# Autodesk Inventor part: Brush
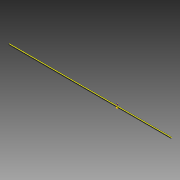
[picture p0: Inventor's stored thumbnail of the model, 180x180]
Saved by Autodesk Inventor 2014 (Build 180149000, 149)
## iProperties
Created: 2006-03
Part Number: Brush
Document SubType Name: Modeling
Designer: debonom
Material: Silicone
Mass: 8.74327 g
Surface Area: 94.4143 cm^2
Volume: 6.99461 cm^3
Density: 1.25 g/cm^3
Appearance: Rubber - Black - Version 1.1
Author: debonom
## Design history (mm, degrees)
sketch "Sketch1"
  geometry: L1 (0, 0)-(-2.332, 5); L2 (-2.332, 5)-(2.332, 5); L3 (2.332, 5)-(0, 0)
  constraints: 6 end point, 1 equal length, 1 horizontal
  dimensions: "d0" = 5 distance from line of L2 L1.start; "d2" = 50 deg angle of L3 L1
extrude "Extrusion1" new body sketch "Sketch1" distance "d3" = 200; taper "d4" = 0 deg
extrude "Extrusion2" join sketch "Sketch1" distance "d5" = 400; taper "d6" = 0 deg
sketch "Sketch2"
  geometry: L1 (0, -2.5)-(0, 15) reference; L2 (-200, 5)-(400, 5) reference; C1 r 2.5 at (0, 10); 1 further point
  constraints: 1 centre point, 1 point on line
  dimensions: "d7" = 5 distance from line of C1.centre L2; "d8" = 5 diameter of C1
workaxis "Work Axis2"
workpoint "Work Point1"
body "Solid1"
